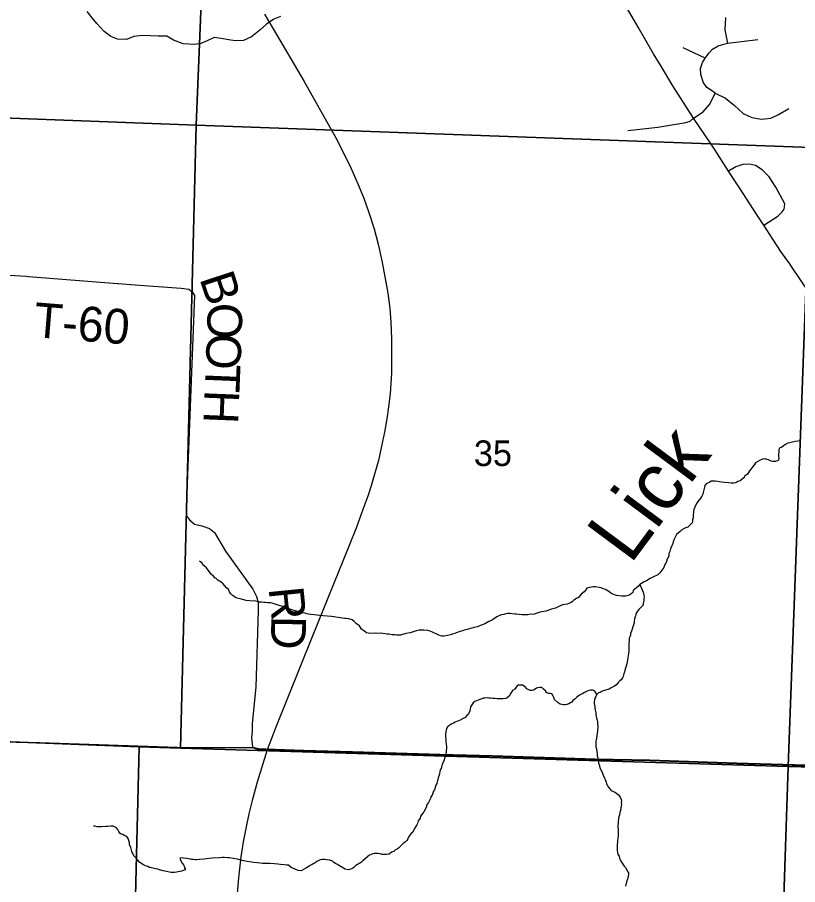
# Model space of a CAD drawing. Extents: x 0 to 34, y 0 to 22.
# Drawn here: x 3.73 to 5.004, y 17.505 to 18.922 of the extents above; entities that cross this region are included whole.
import ezdxf

# ---------------------------------------------------------------- set-up
doc = ezdxf.new("R2010")
doc.units = 0
for name, color, linetype in [('Default', 7, 'Continuous'), ('GM_X_City_Street', 7, 'Continuous'), ('GM_X_Minor_River', 7, 'Continuous'), ('GM_X_Minor_River_Text', 7, 'Continuous'), ('GM_X_Rail_Line', 7, 'Continuous'), ('GM_X_Section', 7, 'Continuous'), ('GM_X_Section_Text', 7, 'Continuous'), ('GM_X_Township_Road', 7, 'Continuous'), ('GM_X_Township_Road_Text', 7, 'Continuous'), ('GM_X_US_Route', 7, 'Continuous')]:
    doc.layers.add(name, color=color, linetype=linetype)

msp = doc.modelspace()

# ---------------------------------------------------------------- linework, layer by layer
at = {"layer": 'Default'}
for points in [[(6.0871, 20.9), (2.1, 20.9), (2.1, 17.8044), (2.8305, 17.7727), (2.976, 17.7664), (3.1037, 17.7609), (3.4544, 17.7458), (3.7662, 17.7368), (3.9904, 17.7296), (4.1165, 17.7286), (4.1238, 17.7269), (4.1354, 17.7264), (4.1969, 17.7246), (4.2769, 17.7222), (4.4203, 17.718), (4.506, 17.7155), (4.6237, 17.7121), (4.6735, 17.7102), (4.763, 17.7084), (4.9045, 17.7039), (4.98, 17.7015), (5.0396, 17.6997)], [(5.0396, 17.6997), (4.98, 17.7015), (4.9045, 17.7039), (4.763, 17.7084), (4.6735, 17.7102), (4.6237, 17.7121), (4.506, 17.7155), (4.4203, 17.718), (4.2769, 17.7222), (4.1969, 17.7246), (4.1354, 17.7264), (4.1238, 17.7269), (4.1165, 17.7286), (3.9904, 17.7296), (3.7662, 17.7368), (3.4544, 17.7458), (3.1037, 17.7609), (2.976, 17.7664), (2.8305, 17.7727), (2.1, 17.8044), (2.1, 14.1), (5.898, 14.1)]]:
    msp.add_lwpolyline(points, dxfattribs=at)
at = {"layer": 'GM_X_City_Street'}
msp.add_line((4.8534, 18.8554), (4.8171, 18.8721), dxfattribs=at)
for points in [[(4.8865, 18.9216), (4.8854, 18.9018), (4.8898, 18.8801)], [(4.8342, 18.7572), (4.8501, 18.7675), (4.8606, 18.7803), (4.8698, 18.7983), (4.8636, 18.8026), (4.8561, 18.8074), (4.8499, 18.8162), (4.8459, 18.8291), (4.8456, 18.8385), (4.8486, 18.848), (4.8534, 18.8554), (4.8597, 18.864), (4.8652, 18.8702), (4.8742, 18.8754), (4.8898, 18.8801), (4.9126, 18.8824), (4.9395, 18.886)], [(4.8698, 18.7983), (4.8862, 18.7898), (4.9014, 18.7779), (4.9154, 18.765), (4.9293, 18.7585), (4.9452, 18.7556), (4.9604, 18.7574), (4.9732, 18.7634), (4.9898, 18.7732)], [(4.7269, 18.7372), (4.7759, 18.7426), (4.8214, 18.7503), (4.8286, 18.7524), (4.8342, 18.7572)]]:
    msp.add_lwpolyline(points, dxfattribs=at)
at = {"layer": 'GM_X_Minor_River'}
for points in [[(4.1596, 18.9236), (4.1487, 18.9192), (4.1368, 18.9111), (4.1256, 18.901), (4.1121, 18.8902), (4.0991, 18.8844), (4.0854, 18.8835), (4.0748, 18.8852), (4.0623, 18.8873), (4.051, 18.889), (4.0399, 18.8835), (4.0295, 18.8795), (4.0193, 18.8774), (4.0098, 18.878), (4.0003, 18.8789), (3.9845, 18.8849), (3.9736, 18.8912), (3.9596, 18.8914), (3.947, 18.892), (3.9334, 18.8926), (3.9201, 18.8906), (3.9078, 18.8859), (3.8934, 18.8865), (3.8821, 18.8905), (3.8716, 18.8987), (3.8594, 18.9118), (3.8516, 18.9214), (3.8434, 18.9318)], [(5.0094, 18.2302), (5.0003, 18.2293), (4.9915, 18.2269), (4.9884, 18.2262), (4.9834, 18.224), (4.9807, 18.2214), (4.9784, 18.22), (4.9746, 18.2182), (4.9734, 18.2159), (4.9731, 18.2053), (4.9734, 18.2015), (4.973, 18.1988), (4.9707, 18.1974), (4.968, 18.1963), (4.9638, 18.1964), (4.9608, 18.1972), (4.9566, 18.1992), (4.9528, 18.2001), (4.9506, 18.2001), (4.9483, 18.2006), (4.946, 18.1999), (4.9429, 18.1988), (4.9352, 18.1941)], [(4.9352, 18.1941), (4.9336, 18.1915), (4.9254, 18.181), (4.9226, 18.1758), (4.9176, 18.1725), (4.9168, 18.1702), (4.9102, 18.1647), (4.9067, 18.1636), (4.9033, 18.1614), (4.9002, 18.1611), (4.8957, 18.1613), (4.8911, 18.1617), (4.885, 18.1623), (4.8805, 18.1628), (4.8767, 18.1632), (4.874, 18.1637), (4.8695, 18.1646), (4.863, 18.1643), (4.8607, 18.1625), (4.8546, 18.16), (4.8526, 18.1574), (4.8522, 18.1547), (4.85, 18.1457), (4.8496, 18.143), (4.8476, 18.1397), (4.846, 18.137), (4.841, 18.1311), (4.839, 18.1277), (4.8362, 18.1217), (4.8346, 18.1183), (4.8341, 18.1153), (4.8336, 18.1073), (4.8335, 18.1047), (4.8327, 18.1017), (4.8326, 18.0994), (4.8318, 18.0964), (4.8287, 18.093), (4.8248, 18.0893), (4.8202, 18.0875), (4.8152, 18.085), (4.8125, 18.0824), (4.8066, 18.0773), (4.805, 18.0739), (4.8022, 18.0686), (4.801, 18.0652), (4.8002, 18.0626), (4.7966, 18.054), (4.7953, 18.0494), (4.7941, 18.046), (4.7936, 18.0419), (4.7912, 18.037), (4.79, 18.0332), (4.7888, 18.0306), (4.7872, 18.028), (4.7856, 18.0235), (4.7809, 18.0171), (4.7793, 18.0149), (4.7758, 18.0115), (4.7735, 18.0101), (4.7712, 18.0094), (4.7666, 18.0068), (4.7635, 18.0054), (4.7573, 18.0018), (4.7535, 18), (4.7492, 17.9974), (4.7465, 17.9956), (4.745, 17.9933), (4.7403, 17.9896), (4.7372, 17.9882), (4.7357, 17.986), (4.7348, 17.9826), (4.7325, 17.9803), (4.7302, 17.9789), (4.7275, 17.9778), (4.7252, 17.9771), (4.7229, 17.9768), (4.7172, 17.9765), (4.7085, 17.9775), (4.7025, 17.98), (4.6991, 17.9816), (4.6961, 17.9843), (4.6905, 17.9875), (4.6867, 17.9883), (4.6833, 17.9899), (4.6803, 17.9908), (4.6742, 17.9917), (4.6704, 17.9918), (4.6677, 17.9915), (4.6643, 17.9908), (4.6601, 17.9897), (4.6581, 17.9868), (4.6554, 17.9834), (4.6507, 17.9797), (4.6464, 17.9745), (4.643, 17.9727), (4.6387, 17.9701), (4.636, 17.9672), (4.6333, 17.9657), (4.6275, 17.9636), (4.6203, 17.9622), (4.6164, 17.9608)], [(4.159, 17.9608), (4.1506, 17.9633), (4.1476, 17.9645), (4.1438, 17.9654), (4.1412, 17.9658), (4.1385, 17.9655), (4.1351, 17.966), (4.1321, 17.966), (4.1283, 17.9665), (4.1252, 17.967), (4.1215, 17.9678), (4.1192, 17.9686), (4.1089, 17.9689), (4.1032, 17.9694), (4.0938, 17.9723), (4.0889, 17.9732), (4.0866, 17.974), (4.0836, 17.976), (4.0806, 17.9783), (4.078, 17.9807), (4.0762, 17.9838), (4.0744, 17.9876), (4.071, 17.9904), (4.0651, 17.997), (4.0625, 17.9993), (4.0569, 18.0029), (4.0546, 18.0052), (4.0524, 18.0064), (4.0502, 18.0091), (4.0468, 18.0118), (4.0446, 18.0149), (4.0383, 18.0227), (4.0327, 18.0278), (4.0317, 18.0305), (4.0272, 18.0336)], [(4.7465, 17.9956), (4.7505, 17.9867), (4.752, 17.9829), (4.753, 17.9783), (4.7533, 17.976), (4.7528, 17.9715), (4.7528, 17.9692), (4.7519, 17.9647), (4.7519, 17.962), (4.7499, 17.9594), (4.7468, 17.9572), (4.7448, 17.9546), (4.7413, 17.9497), (4.7397, 17.9467), (4.7393, 17.9445), (4.7376, 17.9396), (4.7372, 17.935), (4.7371, 17.9328), (4.7359, 17.9297), (4.733, 17.9192), (4.7314, 17.9154), (4.7313, 17.9131), (4.7301, 17.9101), (4.7293, 17.9079), (4.7292, 17.9041), (4.7287, 17.8984), (4.7284, 17.8874), (4.7279, 17.8825), (4.7275, 17.8802), (4.7267, 17.876), (4.7262, 17.8726), (4.7257, 17.8685), (4.7253, 17.8662), (4.7228, 17.8587), (4.722, 17.8549), (4.7215, 17.8522), (4.7204, 17.85), (4.7199, 17.8477), (4.7191, 17.8455), (4.7179, 17.8432), (4.7159, 17.8398), (4.7136, 17.838), (4.7113, 17.8354), (4.7089, 17.8324), (4.705, 17.8295), (4.7027, 17.8284), (4.6997, 17.8266), (4.6966, 17.8244), (4.6943, 17.8241), (4.6889, 17.8227), (4.6851, 17.8212), (4.6816, 17.8194), (4.6789, 17.8184), (4.6762, 17.8161), (4.6746, 17.8124), (4.673, 17.8098), (4.6717, 17.8037), (4.6717, 17.8014), (4.6727, 17.7961), (4.673, 17.7938), (4.6744, 17.7862), (4.6747, 17.7839), (4.6754, 17.7801), (4.6757, 17.7778), (4.6768, 17.774), (4.6771, 17.7717), (4.6774, 17.7671), (4.6777, 17.7641), (4.6775, 17.7561), (4.677, 17.7523), (4.6757, 17.7444), (4.6749, 17.7421), (4.6744, 17.7398), (4.6744, 17.7372), (4.6747, 17.7334), (4.6746, 17.7303), (4.6757, 17.7273), (4.6763, 17.7223), (4.6766, 17.7197), (4.6769, 17.7159), (4.6776, 17.7124), (4.6783, 17.7101), (4.6789, 17.704), (4.68, 17.7013), (4.6818, 17.6948), (4.6836, 17.6914), (4.6854, 17.6872), (4.6868, 17.6841), (4.6886, 17.6795), (4.6901, 17.6772), (4.6908, 17.6745), (4.6926, 17.6691), (4.6937, 17.6668), (4.697, 17.6622), (4.6999, 17.6591), (4.7033, 17.6575), (4.7056, 17.6563), (4.7082, 17.6547), (4.7116, 17.6519), (4.713, 17.6496), (4.7149, 17.6473)], [(4.6164, 17.9608), (4.6087, 17.9568), (4.6022, 17.9555), (4.593, 17.9519), (4.5839, 17.9502), (4.5739, 17.9474), (4.5659, 17.9465), (4.5636, 17.9462), (4.561, 17.9459), (4.5575, 17.946), (4.5541, 17.946), (4.5492, 17.9465), (4.5446, 17.947), (4.542, 17.9471), (4.5374, 17.9476), (4.534, 17.9481), (4.531, 17.9481), (4.5275, 17.9478), (4.5241, 17.9468), (4.5199, 17.9458), (4.513, 17.9429), (4.5076, 17.9392), (4.5041, 17.9367), (4.4999, 17.9352), (4.4933, 17.9316), (4.4906, 17.9305), (4.486, 17.9287), (4.481, 17.9262), (4.4761, 17.9256), (4.4719, 17.9245), (4.4695, 17.9235), (4.4665, 17.9224), (4.4596, 17.921), (4.4554, 17.9193), (4.4523, 17.9186), (4.4496, 17.9175), (4.4466, 17.9164), (4.4443, 17.9154), (4.4404, 17.9143), (4.437, 17.9136), (4.4324, 17.9122), (4.4293, 17.9119), (4.427, 17.9112), (4.4232, 17.9113), (4.421, 17.9118), (4.4183, 17.9126), (4.4157, 17.9138), (4.4086, 17.9174), (4.4037, 17.9194), (4.4003, 17.9206), (4.3938, 17.9212), (4.3858, 17.921), (4.3809, 17.92), (4.3713, 17.9168), (4.3644, 17.9154), (4.3609, 17.9144), (4.3583, 17.9137), (4.356, 17.913), (4.3537, 17.9127), (4.3491, 17.9128), (4.3461, 17.9132), (4.3419, 17.9133), (4.3366, 17.9142), (4.3336, 17.9147), (4.3298, 17.9152), (4.3268, 17.9156), (4.323, 17.9161), (4.3176, 17.9158), (4.3142, 17.9159), (4.3058, 17.9158), (4.3028, 17.9162), (4.3002, 17.9167), (4.2972, 17.9186), (4.2949, 17.9202), (4.2919, 17.9229), (4.2886, 17.9283), (4.2838, 17.9315), (4.2797, 17.935), (4.2763, 17.9378), (4.271, 17.9394), (4.2669, 17.9399), (4.2646, 17.9403), (4.2608, 17.9408), (4.257, 17.9413), (4.2468, 17.9427), (4.243, 17.9432), (4.2293, 17.9446), (4.2229, 17.9452), (4.2191, 17.9453), (4.2092, 17.9467), (4.2054, 17.9471), (4.2028, 17.9476), (4.199, 17.9488), (4.1941, 17.9493), (4.1858, 17.9522), (4.1778, 17.9543), (4.1722, 17.9563), (4.1684, 17.9575), (4.1661, 17.9587), (4.1616, 17.9604), (4.159, 17.9608)], [(4.6762, 17.8161), (4.6729, 17.8215), (4.6695, 17.8231), (4.6661, 17.8232), (4.6634, 17.8225), (4.6604, 17.8215), (4.6561, 17.8193), (4.6534, 17.8175), (4.648, 17.8149), (4.6438, 17.8113), (4.6407, 17.8091), (4.6372, 17.8061), (4.6356, 17.8035), (4.6333, 17.8024), (4.6306, 17.8009), (4.6271, 17.7995), (4.6245, 17.7988), (4.6218, 17.7989), (4.6165, 17.8002), (4.6128, 17.8022), (4.6072, 17.808), (4.6061, 17.8111), (4.605, 17.8134), (4.6028, 17.8168), (4.5998, 17.8177), (4.5971, 17.8177), (4.5941, 17.8193), (4.5923, 17.8217), (4.5889, 17.8248), (4.5863, 17.8271), (4.5833, 17.8272), (4.5799, 17.8269), (4.5776, 17.8262), (4.5753, 17.8247), (4.5726, 17.8229), (4.5703, 17.8222), (4.5672, 17.8223), (4.562, 17.8254), (4.5594, 17.8282), (4.5549, 17.8309), (4.5518, 17.8314), (4.5484, 17.8311), (4.5457, 17.8296), (4.5422, 17.8248), (4.5387, 17.8222), (4.5356, 17.8181), (4.5332, 17.8132), (4.53, 17.8103), (4.5274, 17.8092), (4.5232, 17.8086), (4.5133, 17.8088), (4.5095, 17.8093), (4.5061, 17.8094), (4.5027, 17.8098), (4.4996, 17.8099), (4.497, 17.8104), (4.4932, 17.8101), (4.4905, 17.8098), (4.4882, 17.809), (4.4851, 17.808), (4.4824, 17.8069), (4.477, 17.8044), (4.474, 17.8022), (4.47, 17.7958), (4.4691, 17.7917), (4.4687, 17.789), (4.4671, 17.7856), (4.4659, 17.7834), (4.4636, 17.7816), (4.4609, 17.7786), (4.4566, 17.7764), (4.4528, 17.7742), (4.4505, 17.7731), (4.4447, 17.7706), (4.442, 17.7692), (4.4385, 17.7674), (4.4358, 17.7655), (4.4324, 17.7633), (4.4304, 17.7604), (4.4295, 17.7551), (4.429, 17.7513), (4.429, 17.7486), (4.4296, 17.741), (4.4295, 17.7383), (4.4302, 17.7357), (4.4305, 17.7303), (4.4308, 17.7281), (4.4303, 17.7231), (4.4294, 17.7182), (4.4282, 17.7148), (4.4257, 17.7058), (4.4233, 17.702), (4.4217, 17.6952), (4.4205, 17.6926), (4.4187, 17.6839), (4.4171, 17.6798), (4.415, 17.6707), (4.4134, 17.6677), (4.4113, 17.6602), (4.4094, 17.6579)], [(4.4094, 17.6579), (4.407, 17.6515), (4.405, 17.6486), (4.4045, 17.6463), (4.4013, 17.6395), (4.3978, 17.6354), (4.3978, 17.6324), (4.3934, 17.6242), (4.3883, 17.6174), (4.3878, 17.6137), (4.3843, 17.6096), (4.3831, 17.6054), (4.3822, 17.6028), (4.3783, 17.5972), (4.3771, 17.5946), (4.3755, 17.5908), (4.3724, 17.5882), (4.3692, 17.5837), (4.3673, 17.58), (4.3661, 17.5777), (4.363, 17.5748), (4.3603, 17.5729), (4.3564, 17.5692), (4.3529, 17.5655), (4.3501, 17.5633), (4.3475, 17.5623), (4.3444, 17.5597), (4.3409, 17.5582), (4.337, 17.5553), (4.3324, 17.5543), (4.3256, 17.5548), (4.3222, 17.5557), (4.3188, 17.5561), (4.3161, 17.5562), (4.3127, 17.5563), (4.3104, 17.5556), (4.3047, 17.5534), (4.3023, 17.5512), (4.2942, 17.5442), (4.2918, 17.542), (4.2826, 17.5365), (4.2795, 17.5336), (4.276, 17.5314), (4.2722, 17.5299), (4.2699, 17.5296), (4.2653, 17.5305), (4.2623, 17.5325), (4.2556, 17.5361), (4.2526, 17.538), (4.2492, 17.5396), (4.2466, 17.5416), (4.2443, 17.5435), (4.2394, 17.5452), (4.2353, 17.5461), (4.2311, 17.5465), (4.2277, 17.5462), (4.2242, 17.5456), (4.2189, 17.543), (4.2161, 17.5412), (4.2138, 17.5401), (4.2111, 17.5383), (4.2077, 17.5365), (4.2046, 17.5343), (4.2019, 17.5328), (4.1972, 17.5299), (4.193, 17.5277), (4.1885, 17.5282), (4.1843, 17.5299), (4.1768, 17.5335), (4.1727, 17.537), (4.1697, 17.5374), (4.1655, 17.5379), (4.1594, 17.5384), (4.1549, 17.5389), (4.1495, 17.5391), (4.1423, 17.5396), (4.1302, 17.5399), (4.1268, 17.5404), (4.1161, 17.5414), (4.1048, 17.5432), (4.0968, 17.5449), (4.0893, 17.547), (4.0821, 17.548), (4.0764, 17.5489), (4.0726, 17.5493), (4.0676, 17.5495), (4.0646, 17.5495), (4.0597, 17.5493), (4.0482, 17.5488), (4.0429, 17.5478), (4.0383, 17.5475), (4.0345, 17.5469), (4.0269, 17.5463), (4.0223, 17.546), (4.02, 17.5461), (4.017, 17.5466), (4.0143, 17.5466), (4.0102, 17.5475), (4.0064, 17.5483), (4.0011, 17.5488), (3.9954, 17.549)], [(4.7149, 17.6473), (4.716, 17.6446), (4.7163, 17.6419), (4.7162, 17.6393), (4.7165, 17.6362), (4.7161, 17.634), (4.7148, 17.6264), (4.7139, 17.623), (4.7131, 17.6192), (4.7119, 17.6159), (4.7118, 17.6132), (4.7109, 17.6075), (4.7109, 17.6052), (4.7108, 17.6018), (4.7107, 17.5992), (4.711, 17.5954), (4.7112, 17.5847), (4.7102, 17.5779), (4.7098, 17.5749), (4.7097, 17.5711), (4.7092, 17.5669), (4.7092, 17.5643), (4.7095, 17.5605), (4.7098, 17.5582), (4.7108, 17.5543), (4.7127, 17.5516), (4.7134, 17.5486), (4.7155, 17.5436), (4.7188, 17.5386), (4.721, 17.5355), (4.7229, 17.5332), (4.7255, 17.5297), (4.7265, 17.527), (4.728, 17.5247), (4.728, 17.522), (4.7275, 17.5194), (4.7263, 17.5145), (4.7246, 17.5099), (4.723, 17.5031)], [(3.9954, 17.549), (3.9957, 17.5463), (3.9986, 17.5402), (4.0008, 17.5378), (4.0019, 17.5355), (4.0026, 17.5329), (4.0041, 17.5298), (4.0018, 17.5287), (3.9979, 17.5273), (3.9895, 17.5256), (3.9865, 17.5253), (3.9834, 17.5254), (3.9808, 17.5254), (3.9781, 17.5259), (3.9732, 17.5268), (3.9679, 17.528), (3.9615, 17.5293), (3.9588, 17.5305), (3.9554, 17.5314), (3.9486, 17.5327), (3.9452, 17.5335), (3.9426, 17.5347), (3.9403, 17.5355), (3.9377, 17.5368), (3.9347, 17.5383), (3.9324, 17.5399), (3.9294, 17.5415), (3.9268, 17.5446), (3.9228, 17.5497), (3.9198, 17.5524), (3.9165, 17.5593), (3.9158, 17.5616), (3.9148, 17.5658), (3.913, 17.5708), (3.9127, 17.5735), (3.9116, 17.5777), (3.9105, 17.5807), (3.9083, 17.5838), (3.9042, 17.5858), (3.9016, 17.587), (3.8993, 17.5878), (3.8971, 17.5894), (3.8952, 17.5921), (3.8938, 17.5952), (3.8908, 17.5987), (3.8882, 17.5999), (3.8859, 17.6007), (3.8821, 17.6008), (3.8775, 17.6005), (3.8737, 17.6003), (3.8669, 17.5997), (3.86, 17.5998), (3.8563, 17.6007), (3.854, 17.6011)]]:
    msp.add_lwpolyline(points, dxfattribs=at)
at = {"layer": 'GM_X_Rail_Line'}
msp.add_lwpolyline([(4.1333, 18.9272), (4.1473, 18.9034), (4.198, 18.8174), (4.2498, 18.725), (4.2608, 18.7041), (4.2746, 18.6761), (4.2858, 18.6503), (4.2954, 18.6269), (4.3038, 18.6031), (4.3122, 18.5763), (4.319, 18.5517), (4.3252, 18.5243), (4.3306, 18.4957), (4.3346, 18.4713), (4.3378, 18.4465), (4.3398, 18.4241), (4.341, 18.3969), (4.341, 18.3675), (4.3406, 18.341), (4.3384, 18.3072), (4.336, 18.2856), (4.3331, 18.2664), (4.3294, 18.2444), (4.3246, 18.2217), (4.3196, 18.1983), (4.3131, 18.1756), (4.3076, 18.1567), (4.3022, 18.1398), (4.2942, 18.1181), (4.2828, 18.0878), (4.2714, 18.0595), (4.2112, 17.9103), (4.1516, 17.7628), (4.1375, 17.7254), (4.1213, 17.6729), (4.1131, 17.6428), (4.1079, 17.6209), (4.1033, 17.5999), (4.0985, 17.5753), (4.0949, 17.5505), (4.0908, 17.5163), (4.0873, 17.4782)], dxfattribs=at)
at = {"layer": 'GM_X_Section'}
for points in [[(3.0692, 19.7796), (4.0623, 19.7415), (4.0218, 18.7461), (3.0273, 18.7832)], [(4.0623, 19.7415), (5.0674, 19.7096), (5.0264, 18.7096), (4.0218, 18.7461)], [(3.0273, 18.7832), (4.0218, 18.7461), (3.996, 17.7284), (3.9286, 17.7304), (2.9781, 17.7672)], [(4.0218, 18.7461), (5.0264, 18.7096), (4.989, 17.6982), (3.996, 17.7284)], [(5.0264, 18.7096), (6.0336, 18.6715), (5.9983, 17.6719), (4.989, 17.6982)], [(2.9781, 17.7672), (3.9286, 17.7304), (3.904, 16.7335), (3.4696, 16.7535), (3.47, 16.7707), (2.9224, 16.7901)], [(3.9286, 17.7304), (3.996, 17.7284), (4.989, 17.6982), (4.9556, 16.6985), (3.904, 16.7335)], [(4.989, 17.6982), (5.9983, 17.6719), (5.9708, 16.6629), (4.9556, 16.6985)]]:
    msp.add_lwpolyline(points, close=True, dxfattribs=at)
at = {"layer": 'GM_X_Township_Road'}
msp.add_line((3.6943, 18.502), (3.7438, 18.4991), dxfattribs=at)
for points in [[(4.9489, 18.5828), (4.9719, 18.5975), (4.9792, 18.6042), (4.9825, 18.6089), (4.9831, 18.6173), (4.9685, 18.6444), (4.9577, 18.6615), (4.9466, 18.673), (4.9356, 18.68), (4.9257, 18.6823), (4.9149, 18.6816), (4.9035, 18.6779), (4.8916, 18.6707)], [(3.7438, 18.4991), (3.7478, 18.4989), (3.893, 18.4872)], [(3.893, 18.4872), (3.894, 18.4871), (3.9222, 18.4849), (3.9971, 18.4795), (4.0097, 18.4779), (4.0152, 18.4736), (4.0191, 18.4676), (4.0054, 18.1187), (4.0059, 18.1078), (4.0108, 18.1011), (4.0187, 18.0943), (4.0311, 18.0913), (4.0434, 18.0873), (4.0514, 18.0807), (4.0696, 18.0501), (4.1141, 17.9877), (4.1205, 17.9762), (4.123, 17.9662), (4.123, 17.9533), (4.1193, 17.8281), (4.1133, 17.7686), (4.1131, 17.756), (4.1122, 17.7458), (4.1124, 17.7392)], [(4.1124, 17.7392), (4.1136, 17.7311), (4.1167, 17.728), (4.1241, 17.7263), (4.1356, 17.7258), (4.1971, 17.724), (4.2772, 17.7217), (4.4205, 17.7175), (4.5062, 17.715), (4.6239, 17.7116), (4.6737, 17.7097), (4.7632, 17.7079), (4.9047, 17.7034), (4.9802, 17.701), (5.0399, 17.6991), (5.1255, 17.6967), (5.2209, 17.6936), (5.2739, 17.6918), (5.3127, 17.6904)]]:
    msp.add_lwpolyline(points, dxfattribs=at)
at = {"layer": 'GM_X_US_Route'}
for points in [[(4.8694, 18.7052), (4.8606, 18.7181), (4.8342, 18.7572), (4.8004, 18.8101), (4.7801, 18.844), (4.7689, 18.8623), (4.7439, 18.9059), (4.7149, 18.956), (4.7001, 18.9811), (4.6902, 18.9985), (4.6686, 19.036), (4.64, 19.0836), (4.6234, 19.1132), (4.6123, 19.1319), (4.5996, 19.1539), (4.5858, 19.18), (4.579, 19.1929), (4.5716, 19.2096), (4.5706, 19.2134)], [(5.0213, 18.4746), (5.0109, 18.4902), (4.9931, 18.5166), (4.9903, 18.521), (4.9869, 18.5261), (4.977, 18.5393), (4.964, 18.5595), (4.9489, 18.5828), (4.9383, 18.5988), (4.9201, 18.6265), (4.9162, 18.6326), (4.8916, 18.6707), (4.8723, 18.7009), (4.8694, 18.7052)]]:
    msp.add_lwpolyline(points, dxfattribs=at)

# ---------------------------------------------------------------- texts
at = {"layer": 'GM_X_Minor_River_Text'}
msp.add_text('Lick', height=0.09468, rotation=53.3846, dxfattribs=at).set_placement((4.7309, 18.0268))
at = {"layer": 'GM_X_Section_Text'}
msp.add_text('35', height=0.04186, rotation=0, dxfattribs=at).set_placement((4.4753, 18.1891))
at = {"layer": 'GM_X_Township_Road_Text'}
for s, height, rotation, p in [('B', 0.0568, 288.3783, (4.0266, 18.4955)), ('T-60', 0.05682, 355.4118, (3.7549, 18.3999)), ('O', 0.0568, 268.612, (4.0406, 18.4563)), ('O', 0.0568, 267.6926, (4.0394, 18.4066)), ('T', 0.0568, 267.6927, (4.0374, 18.3566)), ('H', 0.0568, 267.6926, (4.0356, 18.3141)), ('R', 0.0568, 275.7326, (4.1399, 17.9894)), ('D', 0.0568, 269.0268, (4.1445, 17.9447))]:
    msp.add_text(s, height=height, rotation=rotation, dxfattribs=at).set_placement(p)

doc.saveas('drawing.dxf')
